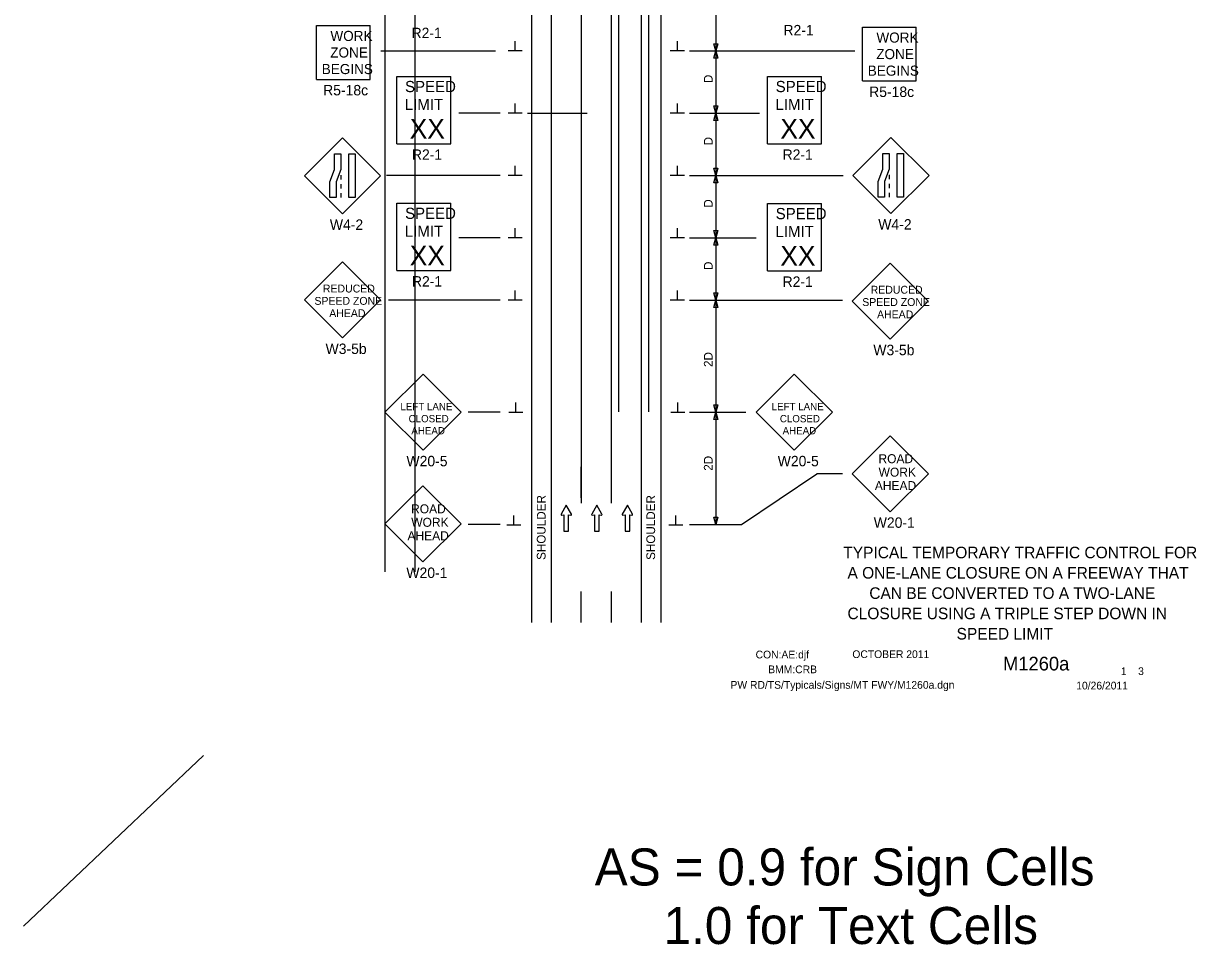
# Model space of a CAD drawing. Extents: x 16503 to 19508, y 5728 to 6974.
# Drawn here: x 16503 to 17444, y 5728 to 6468 of the extents above; entities that cross this region are included whole.
import ezdxf

# ---------------------------------------------------------------- set-up
doc = ezdxf.new("R2010")
doc.units = 0
for name, color, linetype in [('ALI_LEGAL_EX', 7, 'Continuous'), ('BORDER', 7, 'Continuous'), ('BORDER_SIGNAL_WO', 7, 'Continuous'), ('MT_SCRATCH_LEVEL_E', 7, 'Continuous'), ('PAVT_EDGE_EX', 7, 'Continuous'), ('TRAFFIC_SIGNS_PR', 7, 'Continuous'), ('TYPICAL_TEXT_DIMEN_PR', 7, 'Continuous')]:
    doc.layers.add(name, color=color, linetype=linetype)

msp = doc.modelspace()

# ---------------------------------------------------------------- linework, layer by layer
at = {"layer": 'ALI_LEGAL_EX'}
for p, q in [((16980.68, 6974.12), (16980.68, 6155.98)), ((17004.68, 6974.12), (17004.68, 6155.98)), ((16950.77, 6911.88), (16950.77, 6082.69)), ((16974.77, 6911.88), (16974.77, 6082.69)), ((16793.2, 6891.57), (16793.2, 6027.66)), ((16817.2, 6891.57), (16817.2, 6027.66))]:
    msp.add_line(p, q, dxfattribs=at)
for points in [[(16950.77, 6411.88), (16950.77, 6386.88)], [(16974.77, 6411.88), (16974.77, 6386.88)], [(16950.77, 6311.88), (16950.77, 6286.88)], [(16974.77, 6311.88), (16974.77, 6286.88)], [(16950.77, 6211.88), (16950.77, 6186.88)], [(16974.77, 6211.88), (16974.77, 6186.88)], [(16950.77, 6086.88), (16950.77, 6111.88)], [(16950.77, 6086.88), (16950.77, 6111.88)], [(16974.77, 6111.88), (16974.77, 6086.88)], [(16950.77, 5986.88), (16950.77, 6011.88)], [(16950.77, 5986.88), (16950.77, 6011.88)], [(16974.77, 6011.88), (16974.77, 5986.88)]]:
    msp.add_lwpolyline(points, dxfattribs=at)
at = {"layer": 'MT_SCRATCH_LEVEL_E'}
for p, q in [((16938.74, 6081.01), (16934.63, 6073.77)), ((16942.89, 6073.77), (16938.74, 6081.01)), ((16963.3, 6081.01), (16959.19, 6073.77)), ((16967.44, 6073.77), (16963.3, 6081.01)), ((16987.86, 6081.01), (16983.75, 6073.77)), ((16992, 6073.77), (16987.86, 6081.01)), ((16935.11, 6073.08), (16936.89, 6073.4)), ((16936.89, 6073.4), (16936.89, 6060.14)), ((16940.63, 6060.14), (16940.63, 6073.4)), ((16940.63, 6073.4), (16942.41, 6073.08)), ((16959.67, 6073.08), (16961.45, 6073.4)), ((16961.45, 6073.4), (16961.45, 6060.14)), ((16965.19, 6060.14), (16965.19, 6073.4)), ((16965.19, 6073.4), (16966.97, 6073.08)), ((16984.23, 6073.08), (16986.01, 6073.4)), ((16986.01, 6073.4), (16986.01, 6060.14)), ((16989.75, 6060.14), (16989.75, 6073.4)), ((16989.75, 6073.4), (16991.53, 6073.08)), ((16936.89, 6060.14), (16940.63, 6060.14)), ((16961.45, 6060.14), (16965.19, 6060.14)), ((16986.01, 6060.14), (16989.75, 6060.14))]:
    msp.add_line(p, q, dxfattribs=at)
for centre, start, end in [((16935.04, 6073.54), 150.42484, 279.96381), ((16942.48, 6073.54), 260.03619, 29.77312), ((16959.59, 6073.54), 150.42484, 279.96381), ((16967.04, 6073.54), 260.03619, 29.77312), ((16984.15, 6073.54), 150.42484, 279.96381), ((16991.59, 6073.54), 260.03619, 29.77312)]:
    msp.add_arc(centre, 0.463, start, end, dxfattribs=at)
at = {"layer": 'PAVT_EDGE_EX'}
for p, q in [((16910.77, 6923.28), (16910.77, 5986.88)), ((16926.77, 6923.28), (16926.77, 5986.88)), ((16998.77, 6923.28), (16998.77, 5986.88)), ((17014.77, 6923.28), (17014.77, 5986.88))]:
    msp.add_line(p, q, dxfattribs=at)
at = {"layer": 'TRAFFIC_SIGNS_PR'}
for p, q in [((16738.32, 6422.87), (16738.32, 6466.07)), ((16738.32, 6466.07), (16781.52, 6466.07)), ((16781.52, 6422.87), (16781.52, 6466.07)), ((17176.37, 6421.57), (17176.37, 6464.77)), ((17176.37, 6464.77), (17219.57, 6464.77)), ((17219.57, 6421.57), (17219.57, 6464.77)), ((16738.32, 6422.87), (16781.52, 6422.87)), ((16802.96, 6425.14), (16846.16, 6425.14)), ((16802.96, 6371.14), (16802.96, 6425.14)), ((16846.16, 6371.14), (16846.16, 6425.14)), ((17100.32, 6425.14), (17143.52, 6425.14)), ((17100.32, 6371.14), (17100.32, 6425.14)), ((17143.52, 6371.14), (17143.52, 6425.14)), ((17176.37, 6421.57), (17219.57, 6421.57)), ((16759.29, 6375.98), (16728.74, 6345.43)), ((16789.83, 6345.43), (16759.29, 6375.98)), ((17199.27, 6376.24), (17168.72, 6345.69)), ((17229.82, 6345.69), (17199.27, 6376.24)), ((16802.96, 6371.14), (16846.16, 6371.14)), ((17100.32, 6371.14), (17143.52, 6371.14)), ((16728.74, 6345.43), (16759.29, 6314.88)), ((16757.88, 6345.98), (16757.88, 6342.38)), ((16759.29, 6314.88), (16789.83, 6345.43)), ((17168.72, 6345.69), (17199.27, 6315.14)), ((17197.87, 6346.24), (17197.87, 6342.64)), ((17199.27, 6315.14), (17229.82, 6345.69)), ((16757.88, 6338.78), (16757.88, 6335.18)), ((17197.87, 6339.04), (17197.87, 6335.44)), ((16757.88, 6331.58), (16757.88, 6327.98)), ((17197.87, 6331.84), (17197.87, 6328.24)), ((16802.96, 6323.39), (16846.16, 6323.39)), ((16802.96, 6269.39), (16802.96, 6323.39)), ((16846.16, 6269.39), (16846.16, 6323.39)), ((17100.32, 6323.15), (17143.52, 6323.15)), ((17100.32, 6269.15), (17100.32, 6323.15)), ((17143.52, 6269.15), (17143.52, 6323.15)), ((16759.22, 6276.38), (16728.67, 6245.83)), ((16789.77, 6245.83), (16759.22, 6276.38)), ((16802.96, 6269.39), (16846.16, 6269.39)), ((17100.32, 6269.15), (17143.52, 6269.15)), ((17198.71, 6275.4), (17168.16, 6244.86)), ((17229.25, 6244.86), (17198.71, 6275.4)), ((16728.67, 6245.83), (16759.22, 6215.28)), ((16759.22, 6215.28), (16789.77, 6245.83)), ((17168.16, 6244.86), (17198.71, 6214.31)), ((17198.71, 6214.31), (17229.25, 6244.86)), ((16823.87, 6186.24), (16793.32, 6155.69)), ((16854.42, 6155.69), (16823.87, 6186.24)), ((17121.73, 6186.24), (17091.18, 6155.69)), ((17152.27, 6155.69), (17121.73, 6186.24)), ((16793.32, 6155.69), (16823.87, 6125.14)), ((16823.87, 6125.14), (16854.42, 6155.69)), ((17091.18, 6155.69), (17121.73, 6125.14)), ((17121.73, 6125.14), (17152.27, 6155.69)), ((17198.77, 6136.84), (17168.22, 6106.29)), ((17229.31, 6106.29), (17198.77, 6136.84)), ((17168.22, 6106.29), (17198.77, 6075.74)), ((17198.77, 6075.74), (17229.31, 6106.29)), ((16823.81, 6096.58), (16793.26, 6066.04)), ((16854.36, 6066.04), (16823.81, 6096.58)), ((16793.26, 6066.04), (16823.81, 6035.49)), ((16823.81, 6035.49), (16854.36, 6066.04))]:
    msp.add_line(p, q, dxfattribs=at)
for points in [[(16757.88, 6363.14), (16757.88, 6350.56), (16754.12, 6340.56), (16754.12, 6327.98), (16749.07, 6327.98), (16749.07, 6340.56), (16752.83, 6350.56), (16752.83, 6363.14)], [(16769.29, 6363.14), (16769.29, 6327.98), (16764.23, 6327.98), (16764.23, 6363.14)], [(17197.87, 6363.39), (17197.87, 6350.81), (17194.11, 6340.82), (17194.11, 6328.24), (17189.05, 6328.24), (17189.05, 6340.82), (17192.81, 6350.81), (17192.81, 6363.39)], [(17209.27, 6363.39), (17209.27, 6328.24), (17204.22, 6328.24), (17204.22, 6363.39)]]:
    msp.add_lwpolyline(points, close=True, dxfattribs=at)
at = {"layer": 'TYPICAL_TEXT_DIMEN_PR'}
for p, q in [((17058.77, 6495.62), (17058.77, 6445.62)), ((16897.85, 6445.62), (16897.85, 6453.4)), ((17027.9, 6445.62), (17027.9, 6453.4)), ((17058.77, 6445.62), (17057.2, 6451.48)), ((17057.2, 6451.48), (17058.77, 6451.48)), ((17058.77, 6451.48), (17060.34, 6451.48)), ((17060.34, 6451.48), (17058.77, 6445.62)), ((16790.02, 6445.62), (16882.03, 6445.62)), ((16903.47, 6445.62), (16892.22, 6445.62)), ((17033.52, 6445.62), (17022.27, 6445.62)), ((17037.77, 6445.62), (17170.19, 6445.62)), ((17037.77, 6445.62), (17047.02, 6445.62)), ((17057.2, 6439.76), (17058.77, 6445.62)), ((17058.77, 6439.76), (17057.2, 6439.76)), ((17058.77, 6445.62), (17060.34, 6439.76)), ((17058.77, 6445.62), (17058.77, 6395.62)), ((17060.34, 6439.76), (17058.77, 6439.76)), ((16897.85, 6395.62), (16897.85, 6403.4)), ((17027.9, 6395.62), (17027.9, 6403.4)), ((17058.77, 6395.62), (17057.2, 6401.48)), ((17057.2, 6401.48), (17058.77, 6401.48)), ((17058.77, 6401.48), (17060.34, 6401.48)), ((17060.34, 6401.48), (17058.77, 6395.62)), ((16885.71, 6395.62), (16852.63, 6395.62)), ((16903.47, 6395.62), (16892.22, 6395.62)), ((16907.72, 6395.62), (16955.67, 6395.62)), ((17033.52, 6395.62), (17022.27, 6395.62)), ((17037.77, 6395.62), (17093.92, 6395.62)), ((17057.2, 6389.76), (17058.77, 6395.62)), ((17058.77, 6395.62), (17058.77, 6345.62)), ((17058.77, 6395.62), (17060.34, 6389.76)), ((17058.77, 6389.76), (17057.2, 6389.76)), ((17060.34, 6389.76), (17058.77, 6389.76)), ((16897.85, 6345.62), (16897.85, 6353.4)), ((17027.9, 6345.62), (17027.9, 6353.4)), ((16885.71, 6345.62), (16794.44, 6345.62)), ((16903.47, 6345.62), (16892.22, 6345.62)), ((17033.52, 6345.62), (17022.27, 6345.62)), ((17037.77, 6345.62), (17160.92, 6345.62)), ((17037.77, 6345.62), (17047.02, 6345.62)), ((17058.77, 6345.62), (17057.2, 6351.48)), ((17057.2, 6351.48), (17058.77, 6351.48)), ((17057.2, 6339.76), (17058.77, 6345.62)), ((17058.77, 6351.48), (17060.34, 6351.48)), ((17060.34, 6351.48), (17058.77, 6345.62)), ((17058.77, 6345.62), (17060.34, 6339.76)), ((17058.77, 6345.62), (17058.77, 6295.62)), ((17058.77, 6339.76), (17057.2, 6339.76)), ((17060.34, 6339.76), (17058.77, 6339.76)), ((16897.85, 6295.62), (16897.85, 6303.4)), ((17027.9, 6295.62), (17027.9, 6303.4)), ((17058.77, 6295.62), (17057.2, 6301.48)), ((17057.2, 6301.48), (17058.77, 6301.48)), ((17058.77, 6301.48), (17060.34, 6301.48)), ((17060.34, 6301.48), (17058.77, 6295.62)), ((16885.71, 6295.62), (16852.63, 6295.62)), ((16903.47, 6295.62), (16892.22, 6295.62)), ((17033.52, 6295.62), (17022.27, 6295.62)), ((17037.77, 6295.62), (17091.13, 6295.62)), ((17057.2, 6289.76), (17058.77, 6295.62)), ((17058.77, 6289.76), (17057.2, 6289.76)), ((17058.77, 6295.62), (17060.34, 6289.76)), ((17058.77, 6295.62), (17058.77, 6245.62)), ((17060.34, 6289.76), (17058.77, 6289.76)), ((16897.85, 6245.62), (16897.85, 6253.4)), ((16897.85, 6245.62), (16897.85, 6253.4)), ((17027.9, 6245.62), (17027.9, 6253.4)), ((17027.9, 6245.62), (17027.9, 6253.4)), ((17058.77, 6245.62), (17057.2, 6251.48)), ((17057.2, 6251.48), (17058.77, 6251.48)), ((17058.77, 6251.48), (17060.34, 6251.48)), ((17060.34, 6251.48), (17058.77, 6245.62)), ((16885.71, 6245.62), (16796.07, 6245.62)), ((16903.47, 6245.62), (16892.22, 6245.62)), ((16903.47, 6245.62), (16892.22, 6245.62)), ((17033.52, 6245.62), (17022.27, 6245.62)), ((17033.52, 6245.62), (17022.27, 6245.62)), ((17037.77, 6245.62), (17160.37, 6245.62)), ((17037.77, 6245.62), (17063.77, 6245.62)), ((17037.77, 6245.62), (17047.02, 6245.62)), ((17057.2, 6239.76), (17058.77, 6245.62)), ((17058.77, 6245.62), (17058.77, 6155.62)), ((17058.77, 6245.62), (17060.34, 6239.76)), ((17058.77, 6239.76), (17057.2, 6239.76)), ((17060.34, 6239.76), (17058.77, 6239.76)), ((16885.71, 6155.62), (16859.95, 6155.62)), ((16903.87, 6155.57), (16892.62, 6155.57)), ((16898.24, 6155.57), (16898.24, 6163.35)), ((17033.92, 6155.57), (17022.67, 6155.57)), ((17028.29, 6155.57), (17028.29, 6163.35)), ((17037.77, 6155.62), (17082.98, 6155.62)), ((17058.77, 6155.62), (17057.2, 6161.48)), ((17057.2, 6161.48), (17058.77, 6161.48)), ((17057.2, 6149.76), (17058.77, 6155.62)), ((17058.77, 6161.48), (17060.34, 6161.48)), ((17060.34, 6161.48), (17058.77, 6155.62)), ((17058.77, 6155.62), (17058.77, 6065.62)), ((17058.77, 6155.62), (17060.34, 6149.76)), ((17058.77, 6149.76), (17057.2, 6149.76)), ((17060.34, 6149.76), (17058.77, 6149.76)), ((17079.5, 6065.62), (17139.79, 6106.3)), ((17160.37, 6106.3), (17139.79, 6106.3)), ((16896.65, 6065.12), (16896.65, 6072.9)), ((17026.7, 6065.12), (17026.7, 6072.9)), ((17058.77, 6065.62), (17057.2, 6071.48)), ((17057.2, 6071.48), (17058.77, 6071.48)), ((17058.77, 6071.48), (17060.34, 6071.48)), ((17060.34, 6071.48), (17058.77, 6065.62)), ((16885.71, 6065.62), (16859.95, 6065.62)), ((16902.28, 6065.12), (16891.03, 6065.12)), ((17032.33, 6065.12), (17021.08, 6065.12)), ((17037.77, 6065.62), (17079.5, 6065.62)), ((16647.75, 5880), (16503.3, 5743.02))]:
    msp.add_line(p, q, dxfattribs=at)

# ---------------------------------------------------------------- texts
at = {"layer": 'BORDER'}
for s, p in [('TYPICAL TEMPORARY TRAFFIC CONTROL FOR', (17161.04, 6038.42)), ('A ONE-LANE CLOSURE ON A FREEWAY THAT', (17164.42, 6022.12)), ('CAN BE CONVERTED TO A TWO-LANE ', (17181.92, 6005.82)), ('CLOSURE USING A TRIPLE STEP DOWN IN ', (17164.42, 5989.52)), ('SPEED LIMIT', (17251.92, 5973.22))]:
    msp.add_text(s, height=9.3, dxfattribs=at).set_placement(p)
at = {"layer": 'BORDER_SIGNAL_WO'}
for s, height, p in [('CON:AE:djf  ', 6.2, (17090.69, 5958.06)), ('    OCTOBER 2011    ', 6.2, (17159.08, 5958.34)), ('    M1260a   ', 11, (17272.86, 5948.38)), ('BMM:CRB   ', 6.2, (17100.81, 5946.17)), (' 1    3 ', 6.2, (17381.45, 5944.7)), ('PW RD/TS/Typicals/Signs/MT FWY/M1260a.dgn      ', 6.2, (17070.55, 5933.71)), ('10/26/2011    ', 6.2, (17347.93, 5933.13)), ('AS = 0.9 for Sign Cells', 29.7271, (16961.58, 5775.8)), ('     1.0 for Text Cells', 29.7271, (16961.58, 5728.8))]:
    msp.add_text(s, height=height, dxfattribs=at).set_placement(p)
at = {"layer": 'TRAFFIC_SIGNS_PR'}
for s, height, p in [('R2-1', 8.37, (17113.04, 6458.17)), ('WORK', 8.119, (16749.57, 6453.65)), ('R2-1', 8.37, (16814.66, 6455.94)), ('WORK', 8.119, (17187.62, 6452.35)), ('ZONE', 8.119, (16749.44, 6440.37)), ('ZONE', 8.119, (17187.49, 6439.07)), ('BEGINS', 8.119, (16742.61, 6427.08)), ('BEGINS', 8.119, (17180.66, 6425.78)), ('SPEED', 9, (16809.45, 6412.61)), ('SPEED', 9, (17106.81, 6412.61)), ('R5-18c', 8.37, (16743.73, 6410)), ('R5-18c', 8.37, (17181.79, 6408.7)), ('LIMIT', 9, (16809.27, 6398.21)), ('LIMIT', 9, (17106.63, 6398.21)), ('XX', 15.785, (16813.21, 6375.37)), ('XX', 15.785, (17110.57, 6375.37)), ('R2-1', 8.37, (16814.97, 6358.27)), ('R2-1', 8.37, (17112.33, 6358.27)), ('SPEED', 9, (16809.45, 6310.86)), ('SPEED', 9, (17106.81, 6310.62)), ('W4-2', 8.37, (16749.11, 6302.02)), ('W4-2', 8.37, (17189.1, 6302.27)), ('LIMIT', 9, (16809.27, 6296.46)), ('LIMIT', 9, (17106.63, 6296.22)), ('XX', 15.785, (16813.21, 6273.62)), ('XX', 15.785, (17110.57, 6273.37)), ('R2-1', 8.37, (16814.97, 6256.52)), ('R2-1', 8.37, (17112.33, 6256.28)), ('REDUCED', 6.3, (16743.53, 6251.8)), ('REDUCED', 6.3, (17183.02, 6250.83)), ('SPEED ZONE', 6.3, (16736.77, 6241.9)), ('SPEED ZONE', 6.3, (17176.26, 6240.93)), ('AHEAD', 6.3, (16748.65, 6232)), ('AHEAD', 6.3, (17188.14, 6231.03)), ('W3-5b', 8.37, (16745.67, 6202.41)), ('W3-5b', 8.37, (17185.15, 6201.44)), ('LEFT LANE', 5.85, (16805.74, 6157.26)), ('LEFT LANE', 5.85, (17103.59, 6157.26)), ('CLOSED', 5.85, (16812.3, 6147.58)), ('CLOSED', 5.85, (17110.15, 6147.58)), ('AHEAD', 5.85, (16814.49, 6137.91)), ('AHEAD', 5.85, (17112.34, 6137.91)), ('W20-5', 8.37, (16810.57, 6112.27)), ('W20-5', 8.37, (17108.42, 6112.27)), ('ROAD', 7.2, (17189.25, 6114.77)), ('WORK', 7.2, (17189.37, 6103.97)), ('AHEAD', 7.2, (17186.35, 6093.17)), ('ROAD', 7.2, (16814.3, 6074.51)), ('WORK', 7.2, (16814.42, 6063.71)), ('W20-1', 8.37, (17185.46, 6062.87)), ('AHEAD', 7.2, (16811.39, 6052.91)), ('W20-1', 8.37, (16810.5, 6022.62))]:
    msp.add_text(s, height=height, dxfattribs=at).set_placement(p)
at = {"layer": 'TYPICAL_TEXT_DIMEN_PR'}
for s, p in [('D', (17056.21, 6419.84)), ('D', (17056.21, 6369.84)), ('D', (17056.21, 6319.84)), ('D', (17056.21, 6269.84)), ('2D', (17056.21, 6191.98)), ('2D', (17056.21, 6108.7)), ('SHOULDER', (16922.19, 6037.12)), ('SHOULDER', (17010.05, 6037.12))]:
    msp.add_text(s, height=7, rotation=90, dxfattribs=at).set_placement(p)

doc.saveas('drawing.dxf')
